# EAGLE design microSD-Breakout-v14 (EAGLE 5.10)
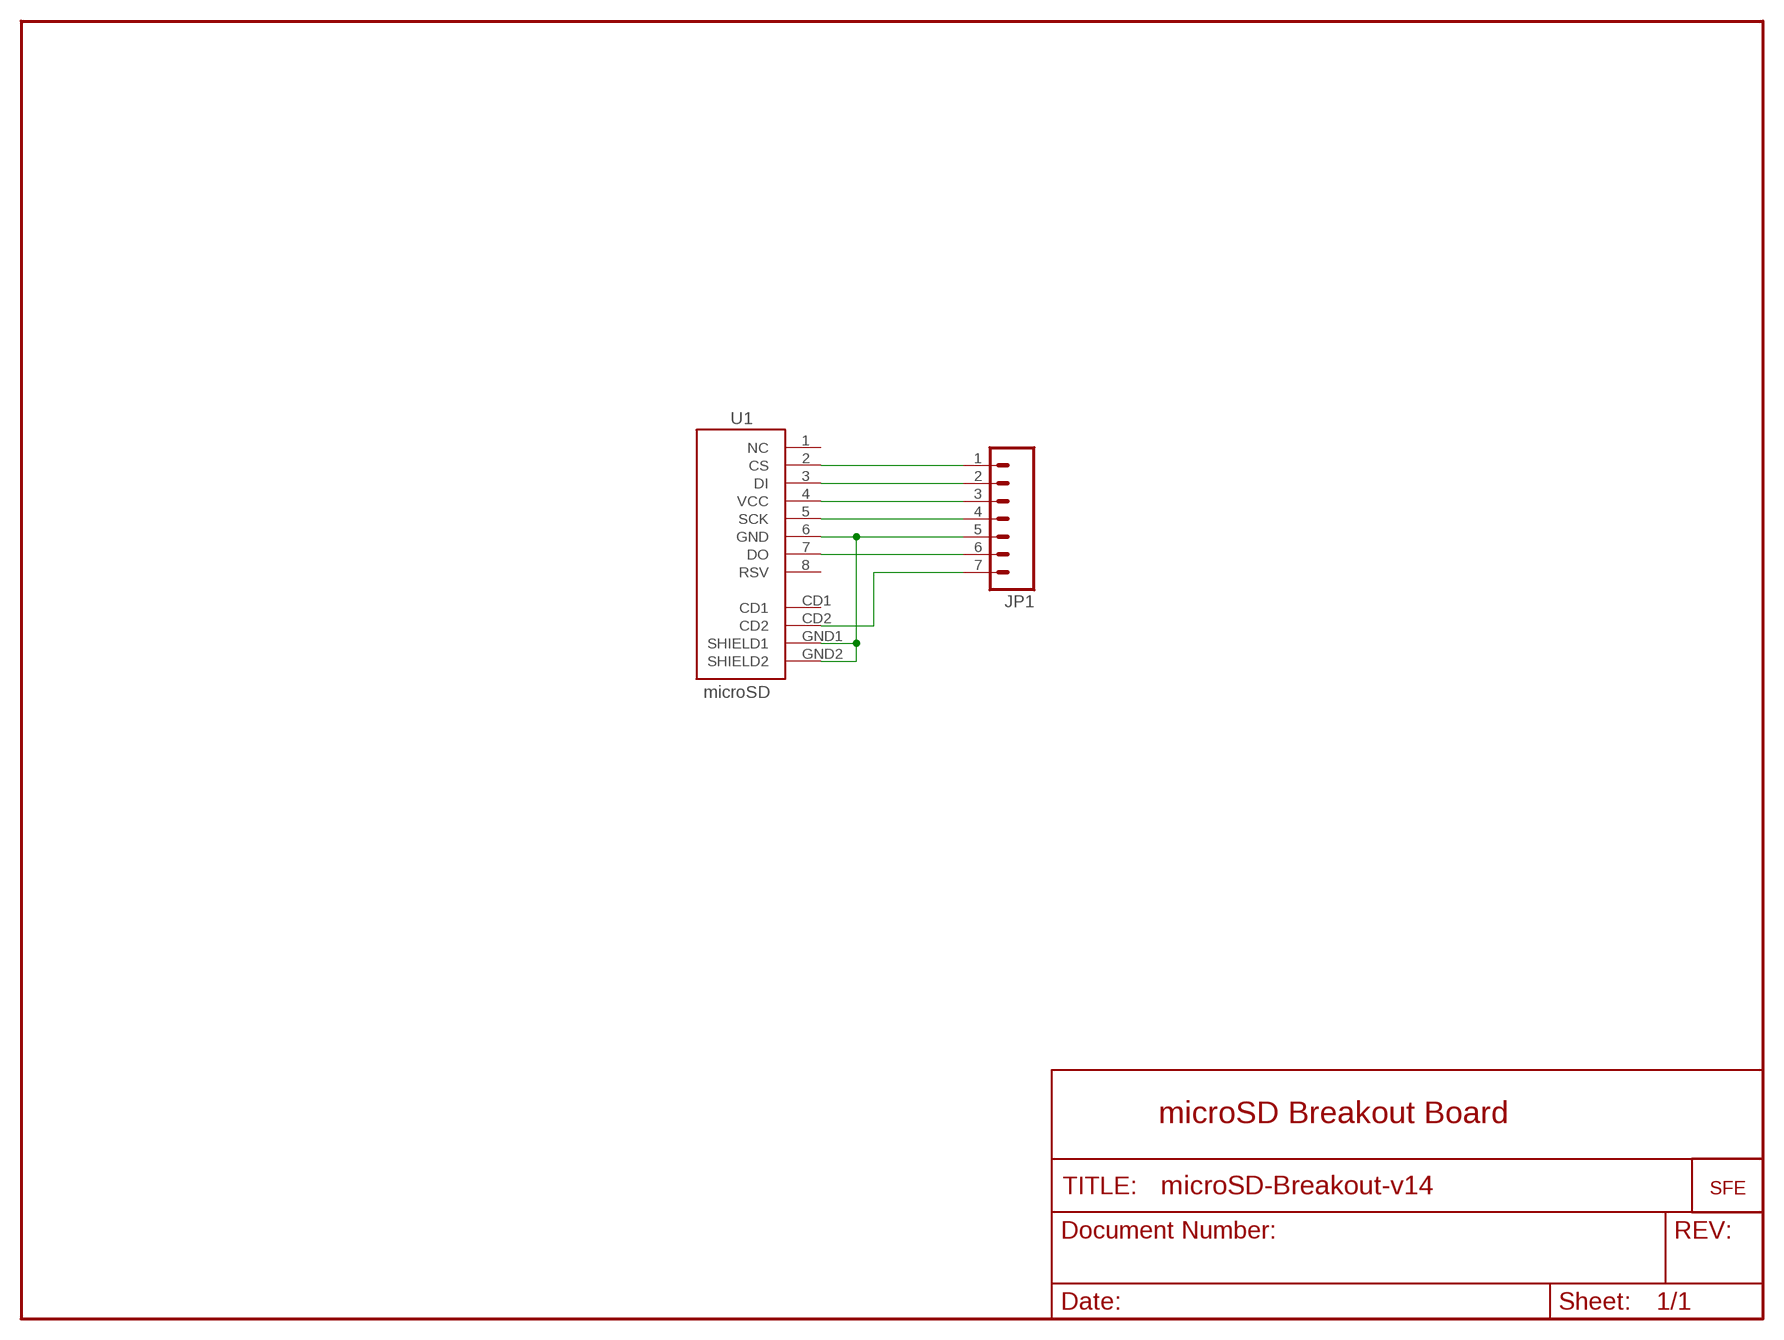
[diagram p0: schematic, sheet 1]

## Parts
JP1  M07  [1X07]
U1  microSD  USD-SOCKETSMD  [MICRO-SD-SOCKET-PP]
U$1  LOGO-SFENEW  [SFE-NEW-WEBLOGO]

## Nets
CD1: JP1.7 U1.CD2
CS: JP1.1 U1.2(CS)
DI: JP1.2 U1.3(DI)
DO: JP1.6 U1.7(DO)
GND: JP1.5 U1.6(GND) U1.GND1(SHIELD1) U1.GND2(SHIELD2)
SCK: JP1.4 U1.5(SCK)
VCC: JP1.3 U1.4(VCC)
Unconnected: U1.1(NC) U1.8(RSV) U1.CD1

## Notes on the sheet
- microSD Breakout Board

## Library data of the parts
JP1 = SparkFun:M07: Header 7 Standard 7-pin 0.1" header. Use with straight break away headers (SKU : PRT-00116), right angle break away headers (PRT-00553), swiss pins (PRT-00743), machine pins (PRT-00117), and female headers (PRT-00115). NOTES ON THE VARIANTS LOCK and LOCK_LONGPADS... This footprint was designed to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
U1 = SparkFun:USD-SOCKET: microSD Socket Push-push type uSD socket. Schematic element and footprint production proven. Spark Fun Electronics SKU : PRT-00127. tDoc lines correctly indicate media card edge positions when inserting (unlocked, locked, depressed).
U$1 = SparkFun:LOGO-SFE: Spark Fun Electronics PCB Logo

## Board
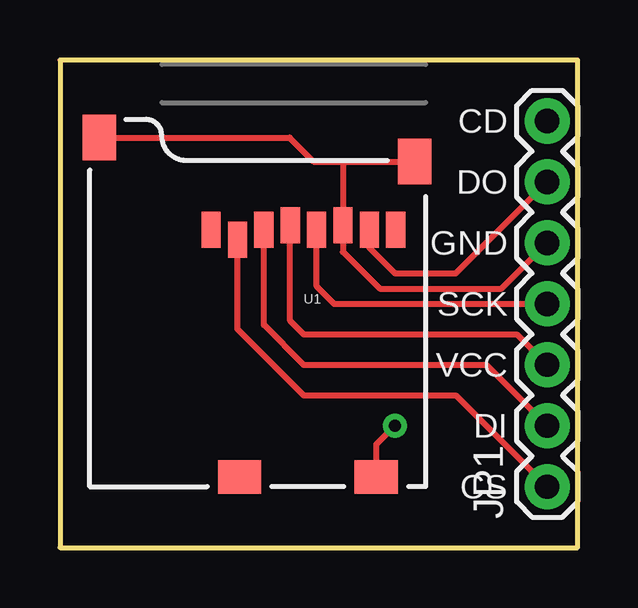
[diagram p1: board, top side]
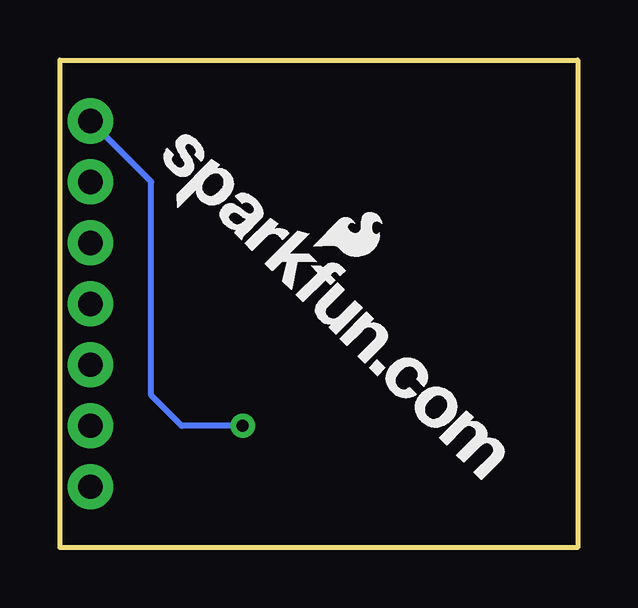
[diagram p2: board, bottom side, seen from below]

Size 21.59 x 20.32 mm. Coordinates in mm from the lower left corner, seen from the top.
Outline: 0,0 21.59,0 21.59,20.32 0,20.32 0,0
Copper layers (1*16): Top 0.035mm / dielectric 1.5mm / Bottom 0.035mm
Design rules "SparkFun": minimum track width 8mil, minimum drill 20mil, track to track 8mil, track to pad 8mil, pad to pad 8mil, via to via 8mil, smd to smd 8mil, copper to edge 10mil, drill to drill 8mil, minimum pad ring 12mil, minimum via ring 10mil, stop-mask expansion 4mil, vias tented up to drill 20mil, thermal gap 10mil

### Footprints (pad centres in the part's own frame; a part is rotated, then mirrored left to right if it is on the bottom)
1X07 = drill 1.016 pad 1.88 round: 1 0,0; 2 2.54,0; 3 5.08,0; 4 7.62,0; 5 10.16,0; 6 12.7,0; 7 15.24,0
MICRO-SD-SOCKET-PP = smd 0.8 x 1.5: 1 -8.94,10.7; 2 -7.84,10.3; 3 -6.74,10.7; 4 -5.64,10.9; 5 -4.54,10.7; 6 -3.44,10.9; 7 -2.34,10.7; 8 -1.24,10.7 | smd 1.8 x 1.4: CD1 -7.75,0.4; CD2 -2.05,0.4 | smd 1.4 x 1.9: GND1 -13.6,14.55; GND2 -0.45,13.55

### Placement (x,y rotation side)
JP1  20.32,2.54 90 top
U1  15.24,2.54 0 top
U$1  18.16,15.62 315 bottom

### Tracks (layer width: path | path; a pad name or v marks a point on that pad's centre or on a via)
CD1  (via drill 0.51)
  Top 0.254: U1.CD2 13.19,4.3 v13.97,5.08
  Bottom 0.254: v13.97,5.08 16.51,5.08 17.78,6.35 17.78,15.24 JP1.7
CS
  Top 0.254: U1.2 7.4,9.11 10.16,6.35 16.51,6.35 JP1.1
DI
  Top 0.254: U1.3 8.5,9.28 10.16,7.62 17.78,7.62 JP1.2
DO
  Top 0.254: U1.7 12.9,12.5 13.97,11.43 16.51,11.43 JP1.6
GND
  Top 0.254: JP1.5 18.41,10.79 13.34,10.79 11.8,12.33 U1.6 11.8,16.08 11.81,16.09 | U1.GND1 9.58,17.09 10.58,16.09 11.81,16.09 | 11.81,16.09 U1.GND2
SCK
  Top 0.254: U1.5 10.7,10.89 11.43,10.16 JP1.4
VCC
  Top 0.254: U1.4 9.6,9.45 10.16,8.89 19.05,8.89 JP1.3

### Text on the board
tPlace: CD | DO | GND | SCK | VCC | DI | CS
